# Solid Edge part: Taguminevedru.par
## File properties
Author: Türk
Template: Iso Part.par
Last saved by: Türk
Revision: 2
Application: Solid Edge
Accuracy: 0,990
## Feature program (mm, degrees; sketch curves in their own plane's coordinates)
helix protrusion "HelixProtrusion_1"  NumberOfTurns = 7
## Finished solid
Body 1: sheet body, 17 faces, 21 edges, 8 vertices.
  Faces by surface: plane 17
  Edges by curve: intersection 13, circle 4, line 4
Body 2: solid body, 7 faces, 18 edges, 12 vertices.
  Faces by surface: plane 4, torus 2, spline 1
  Edges by curve: circle 10, intersection 6, line 2
Bounding box of the edges (mm; curved faces can reach further): 103.000 x 229.400 x 103.000, from (-51.5, 0, -51.5) to (51.5, 229.4, 51.5).
Toroidal faces (ring radius, tube radius in mm): R45.5 r6 x2
Planar faces by outward normal: +y 1, -y 1, oblique 2
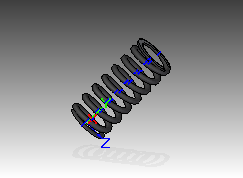
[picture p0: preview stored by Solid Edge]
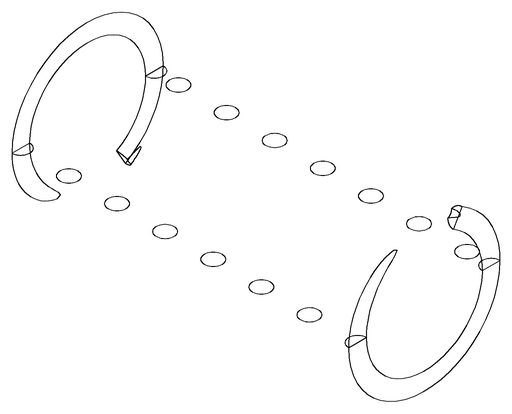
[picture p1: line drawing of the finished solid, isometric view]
